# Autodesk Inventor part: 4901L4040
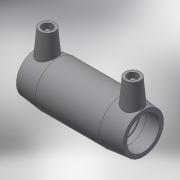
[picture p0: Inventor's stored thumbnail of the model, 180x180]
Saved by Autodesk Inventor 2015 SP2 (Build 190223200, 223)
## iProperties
Created: 2017-06
Part Number: 4901L4040
Material: Generic
Description: PLASSON LONG COUPLER 40
Document SubType Name: Modeling
Designer: KIM
Mass: 72.9589 g
Surface Area: 285.531 cm^2
Volume: 72.9589 cm^3
Density: 1 g/cm^3
Appearance: Default
Author: KIM
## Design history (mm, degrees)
derived "4901L4.ipt"
feature "Solid1::4901L4.ipt"
tag "TaggingFeature1"
body "Solid1"
other parameters: "d0" = 121, "d2" = 56, "d3" = 59, "d4" = 24.2, "d5" = 50.4, "d6" = 32, "d8" = 168 deg, "d10" = 23.6, "d11" = 7.86667, "d29" = 46, "d30" = 15, "d31" = 48.4, "d34" = 5 deg, "d41" = 4, "d42" = 14, "d43" = 0, "d48" = 3, "d49" = 0, "L_" = 121, "L_1" = 59, "D_" = 56, "A_" = 46, "d_2" = 12
